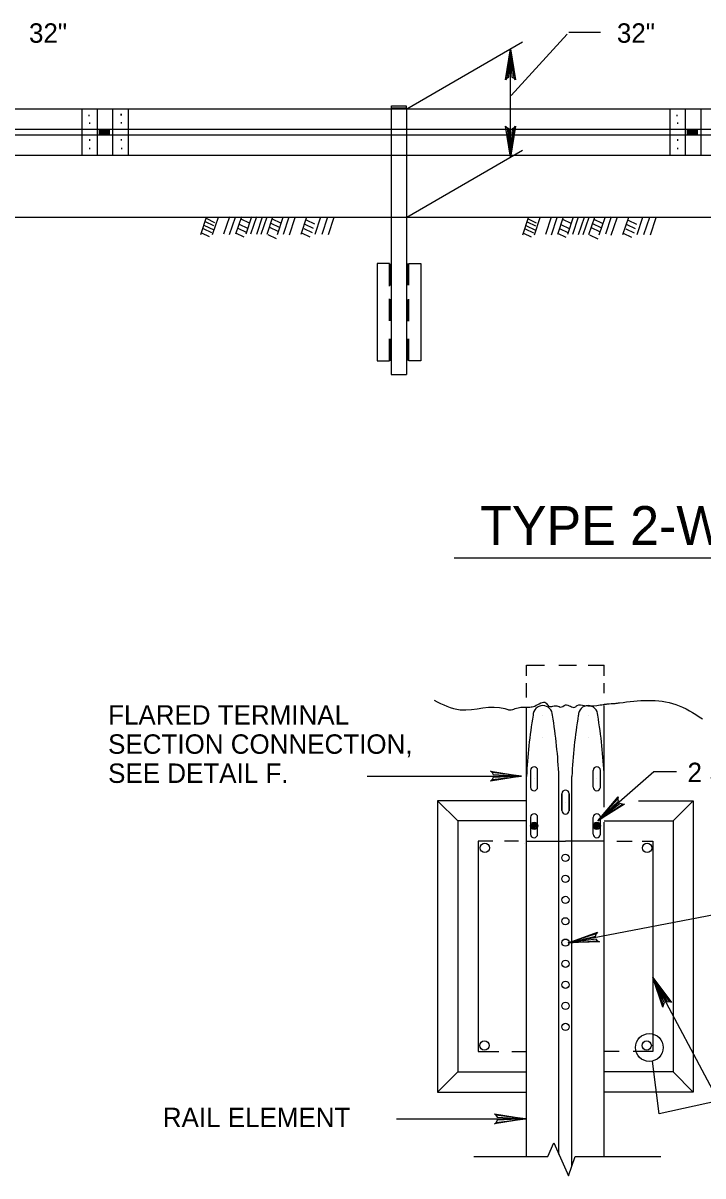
# Model space of a CAD drawing. Extents: x 637628 to 640188, y 298266 to 300751.
# Drawn here: x 638654 to 638759, y 298526 to 298704.1 of the extents above; entities that cross this region are included whole.
import ezdxf

# ---------------------------------------------------------------- set-up
doc = ezdxf.new("R2010")
doc.units = 0
for name, color, linetype in [('1', 7, 'Continuous'), ('2', 7, 'Continuous'), ('3', 7, 'Continuous')]:
    doc.layers.add(name, color=color, linetype=linetype)

msp = doc.modelspace()

# ---------------------------------------------------------------- linework, layer by layer
at = {"layer": '1'}
for p, q in [((638752.29, 298535.63), (638751.25, 298543.79)), ((638761.41, 298537.66), (638752.29, 298535.63))]:
    msp.add_line(p, q, dxfattribs=at)
for centre, radius in [((638725.34, 298576.71), 0.722), ((638750.4, 298576.71), 0.722), ((638750.75, 298545.88), 2.15), ((638725.27, 298546.19), 0.722), ((638750.34, 298546.19), 0.722)]:
    msp.add_circle(centre, radius, dxfattribs=at)
at = {"layer": '2'}
for p, q in [((638713.27, 298690.89), (638731.17, 298701.22)), ((638729.4, 298692.94), (638738.06, 298702.43)), ((638738.31, 298702.69), (638743.2, 298702.69)), ((638729.31, 298683.41), (638729.31, 298700.15)), ((638525.21, 298690.89), (638803.1, 298690.89)), ((638663.06, 298690.89), (638663.06, 298683.7)), ((638665.45, 298690.89), (638665.45, 298683.71)), ((638667.84, 298690.89), (638667.84, 298683.71)), ((638670.23, 298690.89), (638670.23, 298683.7)), ((638710.87, 298690.89), (638710.87, 298683.71)), ((638713.26, 298690.89), (638713.26, 298683.71)), ((638753.9, 298690.89), (638753.9, 298683.7)), ((638756.29, 298690.89), (638756.29, 298683.71)), ((638758.69, 298690.89), (638758.69, 298683.71)), ((638525.21, 298687.73), (638802.53, 298687.73)), ((638525.21, 298686.87), (638802.72, 298686.87)), ((638525.21, 298683.71), (638802.93, 298683.71)), ((638710.87, 298683.71), (638710.87, 298674.15)), ((638713.26, 298683.71), (638713.26, 298674.15)), ((638713.27, 298674.15), (638731.17, 298684.49)), ((638525.21, 298674.15), (638992.56, 298674.15)), ((638682.31, 298674.11), (638681.42, 298671.43)), ((638681.95, 298672.92), (638683.46, 298672.17)), ((638682.16, 298673.49), (638683.42, 298672.86)), ((638682.31, 298673.96), (638683.57, 298673.32)), ((638684.12, 298674.11), (638683.23, 298671.43)), ((638685.88, 298674.2), (638684.99, 298671.52)), ((638686.75, 298674.09), (638685.86, 298671.41)), ((638687.74, 298674.2), (638686.84, 298671.52)), ((638687.37, 298673.08), (638688.65, 298672.43)), ((638687.63, 298673.9), (638688.92, 298673.26)), ((638689.29, 298674.2), (638688.4, 298671.52)), ((638690.05, 298674.2), (638689.15, 298671.52)), ((638690.94, 298674.15), (638690.05, 298671.47)), ((638691.66, 298674.15), (638690.76, 298671.47)), ((638692.53, 298674.15), (638691.64, 298671.47)), ((638692.27, 298673.23), (638693.56, 298672.58)), ((638692.48, 298673.9), (638693.77, 298673.26)), ((638694.14, 298674.11), (638693.25, 298671.43)), ((638695.08, 298674.15), (638694.19, 298671.47)), ((638696, 298674.05), (638695.11, 298671.37)), ((638697.8, 298674.15), (638696.91, 298671.47)), ((638697.54, 298673.08), (638698.82, 298672.43)), ((638697.74, 298673.75), (638699.03, 298673.11)), ((638699.97, 298674.15), (638699.08, 298671.47)), ((638701.04, 298674.15), (638700.15, 298671.47)), ((638702.03, 298674.11), (638701.14, 298671.43)), ((638710.87, 298674.15), (638710.87, 298649.85)), ((638713.26, 298674.15), (638713.26, 298649.85)), ((638732.03, 298674.05), (638731.14, 298671.37)), ((638731.67, 298672.87), (638733.18, 298672.12)), ((638731.88, 298673.43), (638733.14, 298672.8)), ((638732.03, 298673.9), (638733.29, 298673.27)), ((638733.84, 298674.05), (638732.95, 298671.37)), ((638735.6, 298674.15), (638734.71, 298671.47)), ((638736.47, 298674.04), (638735.58, 298671.36)), ((638737.46, 298674.15), (638736.57, 298671.47)), ((638737.09, 298673.02), (638738.37, 298672.38)), ((638737.35, 298673.85), (638738.63, 298673.2)), ((638739.01, 298674.15), (638738.12, 298671.47)), ((638739.77, 298674.15), (638738.87, 298671.47)), ((638740.66, 298674.09), (638739.77, 298671.41)), ((638741.38, 298674.09), (638740.48, 298671.41)), ((638742.26, 298674.09), (638741.36, 298671.41)), ((638741.99, 298673.17), (638743.28, 298672.53)), ((638742.2, 298673.85), (638743.49, 298673.2)), ((638743.86, 298674.05), (638742.97, 298671.37)), ((638744.88, 298674.2), (638743.99, 298671.52)), ((638745.72, 298674), (638744.82, 298671.32)), ((638747.52, 298674.09), (638746.62, 298671.41)), ((638747.26, 298673.02), (638748.54, 298672.38)), ((638747.46, 298673.69), (638748.75, 298673.05)), ((638749.69, 298674.09), (638748.8, 298671.41)), ((638750.76, 298674.09), (638749.87, 298671.41)), ((638751.75, 298674.05), (638750.86, 298671.37)), ((638681.58, 298671.73), (638682.76, 298671.14)), ((638681.84, 298672.4), (638683.13, 298671.76)), ((638686.84, 298671.73), (638688.13, 298671.09)), ((638687.16, 298672.46), (638688.45, 298671.81)), ((638691.81, 298671.47), (638693.09, 298670.82)), ((638692.07, 298672.61), (638693.35, 298671.97)), ((638697.02, 298671.73), (638698.3, 298671.09)), ((638697.39, 298672.4), (638698.67, 298671.76)), ((638731.3, 298671.67), (638732.48, 298671.08)), ((638731.56, 298672.35), (638732.85, 298671.7)), ((638736.57, 298671.67), (638737.85, 298671.03)), ((638736.88, 298672.4), (638738.17, 298671.76)), ((638741.53, 298671.41), (638742.81, 298670.77)), ((638741.79, 298672.55), (638743.07, 298671.91)), ((638746.73, 298671.67), (638748.02, 298671.03)), ((638747.11, 298672.35), (638748.39, 298671.7)), ((638710.75, 298666.94), (638710.75, 298663.57)), ((638713.42, 298666.99), (638713.42, 298663.62)), ((638710.73, 298661.46), (638710.73, 298658.1)), ((638713.37, 298661.44), (638713.37, 298658.07)), ((638710.75, 298655.34), (638710.75, 298651.97)), ((638713.44, 298655.36), (638713.44, 298652)), ((638710.87, 298649.85), (638713.26, 298649.85)), ((638731.79, 298603.31), (638731.79, 298604.94)), ((638731.79, 298604.94), (638734.58, 298604.94)), ((638736.79, 298604.94), (638739.51, 298604.94)), ((638741.29, 298604.94), (638743.79, 298604.94)), ((638743.79, 298603.31), (638743.79, 298604.94)), ((638731.79, 298599.96), (638731.79, 298602.17)), ((638743.79, 298600.59), (638743.79, 298602.17)), ((638731.79, 298529.04), (638731.79, 298598.45)), ((638743.79, 298582.98), (638743.79, 298598.69)), ((638734.29, 298597.19), (638734.29, 298597.19)), ((638741.29, 298597.19), (638741.29, 298597.19)), ((638734.29, 298593.69), (638734.29, 298593.69)), ((638734.29, 298593.69), (638734.29, 298593.69)), ((638736.29, 298593.69), (638736.29, 298593.69)), ((638739.29, 298593.69), (638739.29, 298593.69)), ((638741.29, 298593.69), (638741.29, 298593.69)), ((638741.29, 298593.69), (638741.29, 298593.69)), ((638707.17, 298587.8), (638730.99, 298587.8)), ((638732.39, 298588.68), (638732.39, 298586.06)), ((638732.94, 298587.37), (638732.94, 298587.37)), ((638732.94, 298587.37), (638732.94, 298587.37)), ((638733.5, 298586.1), (638733.5, 298588.68)), ((638736.79, 298529.33), (638736.79, 298587.75)), ((638738.79, 298527.61), (638738.79, 298587.75)), ((638742.07, 298586.1), (638742.07, 298588.68)), ((638742.63, 298587.37), (638742.63, 298587.37)), ((638742.63, 298587.37), (638742.63, 298587.37)), ((638743.18, 298588.68), (638743.18, 298586.06)), ((638721.16, 298580.87), (638718.04, 298584)), ((638737.25, 298582.5), (638737.25, 298585.08)), ((638737.25, 298585.08), (638737.25, 298582.46)), ((638737.8, 298583.77), (638737.8, 298583.77)), ((638737.8, 298583.77), (638737.8, 298583.77)), ((638738.36, 298585.08), (638738.36, 298582.46)), ((638738.36, 298582.5), (638738.36, 298585.08)), ((638754.41, 298580.87), (638757.54, 298584)), ((638732.39, 298581.43), (638732.39, 298578.81)), ((638733.32, 298580.21), (638732.48, 298580.04)), ((638732.88, 298579.66), (638732.48, 298580.18)), ((638732.48, 298580.18), (638733.19, 298579.66)), ((638732.48, 298580.04), (638733.42, 298580.08)), ((638733.17, 298580.47), (638732.52, 298580.25)), ((638732.52, 298580.25), (638733.32, 298580.21)), ((638733.42, 298580.08), (638732.58, 298579.82)), ((638732.64, 298580.47), (638733.17, 298580.47)), ((638733.19, 298579.66), (638732.86, 298580.59)), ((638732.86, 298580.59), (638733.43, 298579.98)), ((638732.94, 298580.12), (638732.94, 298580.12)), ((638732.94, 298580.12), (638732.94, 298580.12)), ((638732.95, 298580.12), (638732.95, 298580.12)), ((638733.43, 298579.98), (638733.26, 298580.53)), ((638733.5, 298578.85), (638733.5, 298581.43)), ((638742.07, 298578.85), (638742.07, 298581.43)), ((638743, 298580.21), (638742.16, 298580.04)), ((638742.57, 298579.66), (638742.16, 298580.18)), ((638742.16, 298580.18), (638742.87, 298579.66)), ((638742.16, 298580.04), (638743.1, 298580.08)), ((638742.86, 298580.47), (638742.2, 298580.25)), ((638742.2, 298580.25), (638743, 298580.21)), ((638743.1, 298580.08), (638742.27, 298579.82)), ((638742.32, 298580.47), (638742.86, 298580.47)), ((638742.87, 298579.66), (638742.54, 298580.59)), ((638742.54, 298580.59), (638743.11, 298579.98)), ((638742.63, 298580.12), (638742.63, 298580.12)), ((638742.63, 298580.12), (638742.63, 298580.12)), ((638742.64, 298580.12), (638742.64, 298580.12)), ((638743.11, 298579.98), (638742.94, 298580.53)), ((638743.18, 298581.43), (638743.18, 298578.81)), ((638743.79, 298529.04), (638743.79, 298580.7)), ((638732.58, 298579.82), (638733.35, 298579.84)), ((638733.35, 298579.84), (638732.88, 298579.66)), ((638742.27, 298579.82), (638743.04, 298579.84)), ((638743.04, 298579.84), (638742.57, 298579.66)), ((638724.29, 298577.75), (638724.29, 298545.25)), ((638726.6, 298577.75), (638724.29, 298577.75)), ((638730.53, 298577.75), (638728.37, 298577.75)), ((638731.54, 298577.32), (638731.54, 298577.32)), ((638731.79, 298577.75), (638737.79, 298577.75)), ((638743.79, 298577.75), (638737.79, 298577.75)), ((638745.72, 298577.75), (638748.12, 298577.75)), ((638749.64, 298577.75), (638751.29, 298577.75)), ((638751.29, 298577.75), (638751.29, 298545.25)), ((638761.41, 298537.66), (638751.27, 298556.71)), ((638724.29, 298545.25), (638727.49, 298545.25)), ((638729.51, 298545.25), (638731.79, 298545.25)), ((638746.1, 298545.25), (638743.79, 298545.25)), ((638751.29, 298545.25), (638748.25, 298545.25)), ((638721.16, 298542.12), (638718.04, 298539)), ((638754.41, 298542.12), (638757.54, 298539)), ((638711.7, 298534.86), (638731.6, 298534.86)), ((638723.66, 298529.04), (638735.06, 298529.04)), ((638739.29, 298529.04), (638752.55, 298529.04))]:
    msp.add_line(p, q, dxfattribs=at)
for points in [[(638728.74, 298695.61), (638729.07, 298695.78), (638729.31, 298700.15), (638728.74, 298695.61), (638728.54, 298695.37), (638729.31, 298700.15), (638729.53, 298695.78), (638729.85, 298695.62), (638729.31, 298700.15), (638730.07, 298695.37), (638729.85, 298695.62)], [(638729.88, 298687.95), (638729.55, 298687.78), (638729.31, 298683.41), (638729.88, 298687.95), (638730.08, 298688.19), (638729.31, 298683.41), (638729.1, 298687.78), (638728.77, 298687.94), (638729.31, 298683.41), (638728.55, 298688.19), (638728.77, 298687.94)], [(638710.59, 298663.5), (638710.59, 298666.96), (638708.73, 298666.96), (638708.73, 298651.96), (638710.59, 298651.96), (638710.59, 298655.33)], [(638713.58, 298663.63), (638713.58, 298666.97), (638715.44, 298666.97), (638715.44, 298651.97), (638713.58, 298651.97), (638713.58, 298655.36)], [(638710.59, 298658.13), (638710.59, 298661.52)], [(638713.58, 298658.07), (638713.58, 298661.46)], [(638726.45, 298588.37), (638726.62, 298588.04), (638730.99, 298587.8), (638726.45, 298588.37), (638726.22, 298588.57), (638730.99, 298587.8), (638726.62, 298587.58), (638726.46, 298587.26), (638730.99, 298587.8), (638726.22, 298587.04), (638726.46, 298587.26)], [(638754.93, 298588.45), (638751.47, 298588.45), (638742.82, 298580.89)], [(638731.79, 298584), (638718.04, 298584), (638718.04, 298539), (638731.79, 298539)], [(638746.61, 298583.45), (638746.27, 298583.59), (638742.82, 298580.89), (638746.61, 298583.45), (638746.92, 298583.45), (638742.82, 298580.89), (638745.97, 298583.93), (638745.87, 298584.28), (638742.82, 298580.89), (638745.92, 298584.6), (638745.87, 298584.28)], [(638749.07, 298584), (638757.54, 298584), (638757.54, 298539), (638743.79, 298539)], [(638731.79, 298580.87), (638721.16, 298580.87), (638721.16, 298542.12), (638731.79, 298542.12)], [(638743.79, 298580.87), (638754.41, 298580.87), (638754.41, 298542.12), (638743.79, 298542.12)], [(638767.35, 298566.79), (638763.44, 298566.88), (638738.19, 298562.04)], [(638742.76, 298562.34), (638742.53, 298562.63), (638738.19, 298562.04), (638742.76, 298562.34), (638743.03, 298562.18), (638738.19, 298562.04), (638742.44, 298563.08), (638742.54, 298563.43), (638738.19, 298562.04), (638742.74, 298563.69), (638742.54, 298563.43)], [(638752.9, 298552.43), (638753.11, 298552.74), (638751.27, 298556.71), (638752.9, 298552.43), (638752.84, 298552.13), (638751.27, 298556.71), (638753.52, 298552.95), (638753.88, 298552.97), (638751.27, 298556.71), (638754.19, 298552.85), (638753.88, 298552.97)], [(638727.05, 298535.43), (638727.23, 298535.1), (638731.6, 298534.86), (638727.05, 298535.43), (638726.82, 298535.63), (638731.6, 298534.86), (638727.23, 298534.64), (638727.07, 298534.31), (638731.6, 298534.86), (638726.82, 298534.1), (638727.07, 298534.31)], [(638735.06, 298529.04), (638735.98, 298531.15), (638738.24, 298526.04), (638739.29, 298529.04)]]:
    msp.add_lwpolyline(points, dxfattribs=at)
for points in [[(638710.92, 298690.95), (638710.92, 298691.34), (638713.18, 298691.34), (638713.18, 298690.95)], [(638665.83, 298686.91), (638665.83, 298687.69), (638667.3, 298687.69), (638667.3, 298686.91)], [(638665.86, 298686.93), (638665.86, 298687.67), (638667.26, 298687.67), (638667.26, 298686.93)], [(638665.88, 298686.96), (638665.88, 298687.66), (638667.21, 298687.66), (638667.21, 298686.96)], [(638665.91, 298686.97), (638665.91, 298687.64), (638667.17, 298687.64), (638667.17, 298686.97)], [(638665.93, 298686.99), (638665.93, 298687.63), (638667.13, 298687.63), (638667.13, 298686.99)], [(638665.96, 298687.01), (638665.96, 298687.61), (638667.1, 298687.61), (638667.1, 298687.01)], [(638665.98, 298687.03), (638665.98, 298687.6), (638667.06, 298687.6), (638667.06, 298687.03)], [(638666, 298687.04), (638666, 298687.58), (638667.03, 298687.58), (638667.03, 298687.04)], [(638666.02, 298687.06), (638666.02, 298687.57), (638667, 298687.57), (638667, 298687.06)], [(638666.04, 298687.07), (638666.04, 298687.56), (638666.97, 298687.56), (638666.97, 298687.07)], [(638666.06, 298687.08), (638666.06, 298687.54), (638666.95, 298687.54), (638666.95, 298687.08)], [(638666.09, 298687.09), (638666.09, 298687.53), (638666.93, 298687.53), (638666.93, 298687.09)], [(638666.11, 298687.1), (638666.11, 298687.52), (638666.91, 298687.52), (638666.91, 298687.1)], [(638666.13, 298687.11), (638666.13, 298687.51), (638666.89, 298687.51), (638666.89, 298687.11)], [(638666.15, 298687.12), (638666.15, 298687.5), (638666.87, 298687.5), (638666.87, 298687.12)], [(638666.17, 298687.13), (638666.17, 298687.49), (638666.86, 298687.49), (638666.86, 298687.13)], [(638666.19, 298687.13), (638666.19, 298687.48), (638666.84, 298687.48), (638666.84, 298687.13)], [(638666.21, 298687.14), (638666.21, 298687.47), (638666.83, 298687.47), (638666.83, 298687.14)], [(638666.22, 298687.15), (638666.22, 298687.46), (638666.81, 298687.46), (638666.81, 298687.15)], [(638666.24, 298687.16), (638666.24, 298687.45), (638666.8, 298687.45), (638666.8, 298687.16)], [(638666.26, 298687.16), (638666.26, 298687.44), (638666.79, 298687.44), (638666.79, 298687.16)], [(638666.27, 298687.17), (638666.27, 298687.43), (638666.77, 298687.43), (638666.77, 298687.17)], [(638666.29, 298687.18), (638666.29, 298687.43), (638666.76, 298687.43), (638666.76, 298687.18)], [(638666.3, 298687.18), (638666.3, 298687.42), (638666.75, 298687.42), (638666.75, 298687.18)], [(638666.31, 298687.19), (638666.31, 298687.41), (638666.74, 298687.41), (638666.74, 298687.19)], [(638666.32, 298687.19), (638666.32, 298687.41), (638666.73, 298687.41), (638666.73, 298687.19)], [(638666.33, 298687.2), (638666.33, 298687.4), (638666.72, 298687.4), (638666.72, 298687.2)], [(638666.34, 298687.2), (638666.34, 298687.4), (638666.71, 298687.4), (638666.71, 298687.2)], [(638666.35, 298687.21), (638666.35, 298687.39), (638666.7, 298687.39), (638666.7, 298687.21)], [(638666.36, 298687.21), (638666.36, 298687.39), (638666.7, 298687.39), (638666.7, 298687.21)], [(638666.37, 298687.22), (638666.37, 298687.38), (638666.69, 298687.38), (638666.69, 298687.22)], [(638666.38, 298687.22), (638666.38, 298687.38), (638666.68, 298687.38), (638666.68, 298687.22)], [(638666.39, 298687.22), (638666.39, 298687.37), (638666.67, 298687.37), (638666.67, 298687.22)], [(638666.4, 298687.23), (638666.4, 298687.37), (638666.67, 298687.37), (638666.67, 298687.23)], [(638666.4, 298687.23), (638666.4, 298687.37), (638666.66, 298687.37), (638666.66, 298687.23)], [(638756.67, 298686.91), (638756.67, 298687.69), (638758.14, 298687.69), (638758.14, 298686.91)], [(638756.7, 298686.93), (638756.7, 298687.67), (638758.1, 298687.67), (638758.1, 298686.93)], [(638756.73, 298686.96), (638756.73, 298687.66), (638758.06, 298687.66), (638758.06, 298686.96)], [(638756.75, 298686.97), (638756.75, 298687.64), (638758.01, 298687.64), (638758.01, 298686.97)], [(638756.78, 298686.99), (638756.78, 298687.63), (638757.98, 298687.63), (638757.98, 298686.99)], [(638756.8, 298687.01), (638756.8, 298687.61), (638757.94, 298687.61), (638757.94, 298687.01)], [(638756.82, 298687.03), (638756.82, 298687.6), (638757.9, 298687.6), (638757.9, 298687.03)], [(638756.84, 298687.04), (638756.84, 298687.58), (638757.87, 298687.58), (638757.87, 298687.04)], [(638756.86, 298687.06), (638756.86, 298687.57), (638757.84, 298687.57), (638757.84, 298687.06)], [(638756.88, 298687.07), (638756.88, 298687.56), (638757.81, 298687.56), (638757.81, 298687.07)], [(638756.91, 298687.08), (638756.91, 298687.54), (638757.79, 298687.54), (638757.79, 298687.08)], [(638756.93, 298687.09), (638756.93, 298687.53), (638757.77, 298687.53), (638757.77, 298687.09)], [(638756.95, 298687.1), (638756.95, 298687.52), (638757.75, 298687.52), (638757.75, 298687.1)], [(638756.98, 298687.11), (638756.98, 298687.51), (638757.73, 298687.51), (638757.73, 298687.11)], [(638757, 298687.12), (638757, 298687.5), (638757.71, 298687.5), (638757.71, 298687.12)], [(638757.02, 298687.13), (638757.02, 298687.49), (638757.7, 298687.49), (638757.7, 298687.13)], [(638757.04, 298687.13), (638757.04, 298687.48), (638757.69, 298687.48), (638757.69, 298687.13)], [(638757.05, 298687.14), (638757.05, 298687.47), (638757.67, 298687.47), (638757.67, 298687.14)], [(638757.07, 298687.15), (638757.07, 298687.46), (638757.66, 298687.46), (638757.66, 298687.15)], [(638757.09, 298687.16), (638757.09, 298687.45), (638757.64, 298687.45), (638757.64, 298687.16)], [(638757.1, 298687.16), (638757.1, 298687.44), (638757.63, 298687.44), (638757.63, 298687.16)], [(638757.12, 298687.17), (638757.12, 298687.43), (638757.62, 298687.43), (638757.62, 298687.17)], [(638757.13, 298687.18), (638757.13, 298687.43), (638757.61, 298687.43), (638757.61, 298687.18)], [(638757.14, 298687.18), (638757.14, 298687.42), (638757.6, 298687.42), (638757.6, 298687.18)], [(638757.15, 298687.19), (638757.15, 298687.41), (638757.59, 298687.41), (638757.59, 298687.19)], [(638757.17, 298687.19), (638757.17, 298687.41), (638757.58, 298687.41), (638757.58, 298687.19)], [(638757.18, 298687.2), (638757.18, 298687.4), (638757.56, 298687.4), (638757.56, 298687.2)], [(638757.19, 298687.2), (638757.19, 298687.4), (638757.56, 298687.4), (638757.56, 298687.2)], [(638757.2, 298687.21), (638757.2, 298687.39), (638757.55, 298687.39), (638757.55, 298687.21)], [(638757.21, 298687.21), (638757.21, 298687.39), (638757.54, 298687.39), (638757.54, 298687.21)], [(638757.22, 298687.22), (638757.22, 298687.38), (638757.53, 298687.38), (638757.53, 298687.22)], [(638757.23, 298687.22), (638757.23, 298687.38), (638757.53, 298687.38), (638757.53, 298687.22)], [(638757.23, 298687.22), (638757.23, 298687.37), (638757.52, 298687.37), (638757.52, 298687.22)], [(638757.24, 298687.23), (638757.24, 298687.37), (638757.51, 298687.37), (638757.51, 298687.23)], [(638757.25, 298687.23), (638757.25, 298687.37), (638757.51, 298687.37), (638757.51, 298687.23)]]:
    msp.add_lwpolyline(points, close=True, dxfattribs=at)
for centre, radius in [((638732.95, 298580.12), 0.569), ((638742.63, 298580.12), 0.569), ((638737.79, 298575.18), 0.553), ((638737.79, 298571.93), 0.553), ((638737.79, 298568.68), 0.553), ((638737.78, 298565.38), 0.553), ((638737.8, 298562.08), 0.553), ((638737.8, 298558.81), 0.553), ((638737.8, 298555.57), 0.553), ((638737.8, 298552.32), 0.553), ((638737.8, 298549.06), 0.553)]:
    msp.add_circle(centre, radius, dxfattribs=at)
for centre, radius, start, end in [((638734.29, 298597.19), 1.5, 0, 180), ((638741.29, 298597.19), 1.5, 0, 180), ((638813.63, 298583.86), 81.94, 170.6336, 177.279), ((638654.94, 298583.86), 81.94, 2.721, 9.3664), ((638820.63, 298583.86), 81.94, 170.6336, 177.279), ((638661.94, 298583.86), 81.94, 2.721, 9.3664), ((638732.94, 298588.68), 0.554, 0.6286, 178.7414), ((638742.63, 298588.68), 0.554, 1.2586, 179.3714), ((638732.94, 298586.09), 0.554, 183.1764, 1.2759), ((638737.8, 298585.08), 0.554, 1.2586, 179.3714), ((638737.8, 298585.08), 0.554, 0.6286, 178.7414), ((638742.63, 298586.09), 0.554, 178.7241, 356.8236), ((638732.94, 298581.43), 0.554, 0.6286, 178.7414), ((638737.8, 298582.5), 0.554, 178.7241, 356.8236), ((638737.8, 298582.5), 0.554, 183.1764, 1.2759), ((638742.63, 298581.43), 0.554, 1.2586, 179.3714), ((638732.94, 298578.84), 0.554, 183.1764, 1.2759), ((638742.63, 298578.84), 0.554, 178.7241, 356.8236)]:
    msp.add_arc(centre, radius, start, end, dxfattribs=at)
msp.add_spline([(638717.49, 298599.51), (638721.54, 298598.06), (638728.45, 298598.22), (638729.02, 298598.05), (638729.43, 298598.05), (638730.25, 298598.3), (638731.15, 298598.46), (638732.3, 298598.46), (638733.04, 298598.63), (638734.75, 298599.12), (638735.16, 298598.63), (638736.64, 298598.63), (638736.97, 298598.46), (638737.79, 298598.79), (638739.26, 298598.46), (638739.59, 298598.71), (638740.74, 298598.71), (638742.62, 298598.71), (638743.68, 298598.87), (638744.26, 298598.95), (638745.49, 298599.04), (638746.14, 298599.12), (638754.83, 298598.88), (638758.95, 298596.66)], degree=3, dxfattribs=at)
at = {"layer": '3'}
msp.add_line((638720.61, 298621.52), (638904.56, 298621.52), dxfattribs=at)

# ---------------------------------------------------------------- texts
for s, height, p in [('32"', 3, (638654.92, 298701.08)), ('32"', 3, (638745.74, 298701.08)), ('.', 1.72, (638663.88, 298689.72)), ('.', 1.72, (638663.96, 298688.51)), ('.', 1.72, (638668.84, 298689.84)), ('.', 1.72, (638668.86, 298688.57)), ('.', 1.72, (638754.72, 298689.72)), ('.', 1.72, (638754.8, 298688.51)), ('.', 1.72, (638663.97, 298685.92)), ('.', 1.72, (638668.86, 298685.95)), ('.', 1.72, (638754.82, 298685.92)), ('.', 1.72, (638663.96, 298684.6)), ('.', 1.72, (638668.93, 298684.61)), ('.', 1.72, (638754.8, 298684.6)), ('TYPE 2-WEAK POST END TREATMENT', 6, (638724.61, 298623.51)), ('FLARED TERMINAL', 3, (638667.14, 298595.75)), ('SECTION CONNECTION,', 3, (638667.14, 298591.25)), ('SEE DETAIL F.', 3, (638667.14, 298586.75)), ('2 SPLICE BOLTS AND NUTS', 3, (638756.65, 298586.87)), ('RAIL ELEMENT', 3, (638675.59, 298533.58))]:
    msp.add_text(s, height=height, dxfattribs=at).set_placement(p)

doc.saveas('drawing.dxf')
